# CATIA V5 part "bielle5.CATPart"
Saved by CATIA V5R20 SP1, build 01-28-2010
Part number: bielle5
Bounding box of the stored display mesh (mm): x -192.802 to -133.802, y 0 to 5, z 48.093 to 61.907
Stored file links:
  E:\EDELI\gcausse\Edeli_2012_184_gcausse\bielle5.CATPart
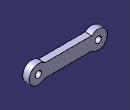
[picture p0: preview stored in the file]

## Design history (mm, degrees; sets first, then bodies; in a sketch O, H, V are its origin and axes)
Body1 (main body)
  Sketch1 on zx-plane, origin (0, 0, 0), H (-1, 0, 0), V (0, 0, 1)
    line L1 (180.9026, 60) -> (145.7005, 60)
    line L2 (180.9026, 50) -> (145.7005, 50)
    arc A1 centre (185.8015, 55) radius 7 from (180.9026, 60) to (180.9026, 50) cw
    point P5 (185.8015, 55)
    arc A2 centre (140.8015, 55) radius 7 from (145.7005, 60) to (145.7005, 50) ccw
    point P6 (140.8015, 55)
    circle A3 centre (140.8015, 55) radius 2.5
    circle A4 centre (185.8015, 55) radius 2.5
    radius A2 = 7
    radius A1 = 7
    distance L1 L2 = 10
    distance P5 L1 = 5
    distance P6 L1 = 5
    distance P6 P5 = 45
    radius A3 = 2.5
    radius A4 = 2.5
    horizontal: L1 H, L2 H
  Pad1: profile Sketch1, direction (0, 1, 0), length 5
